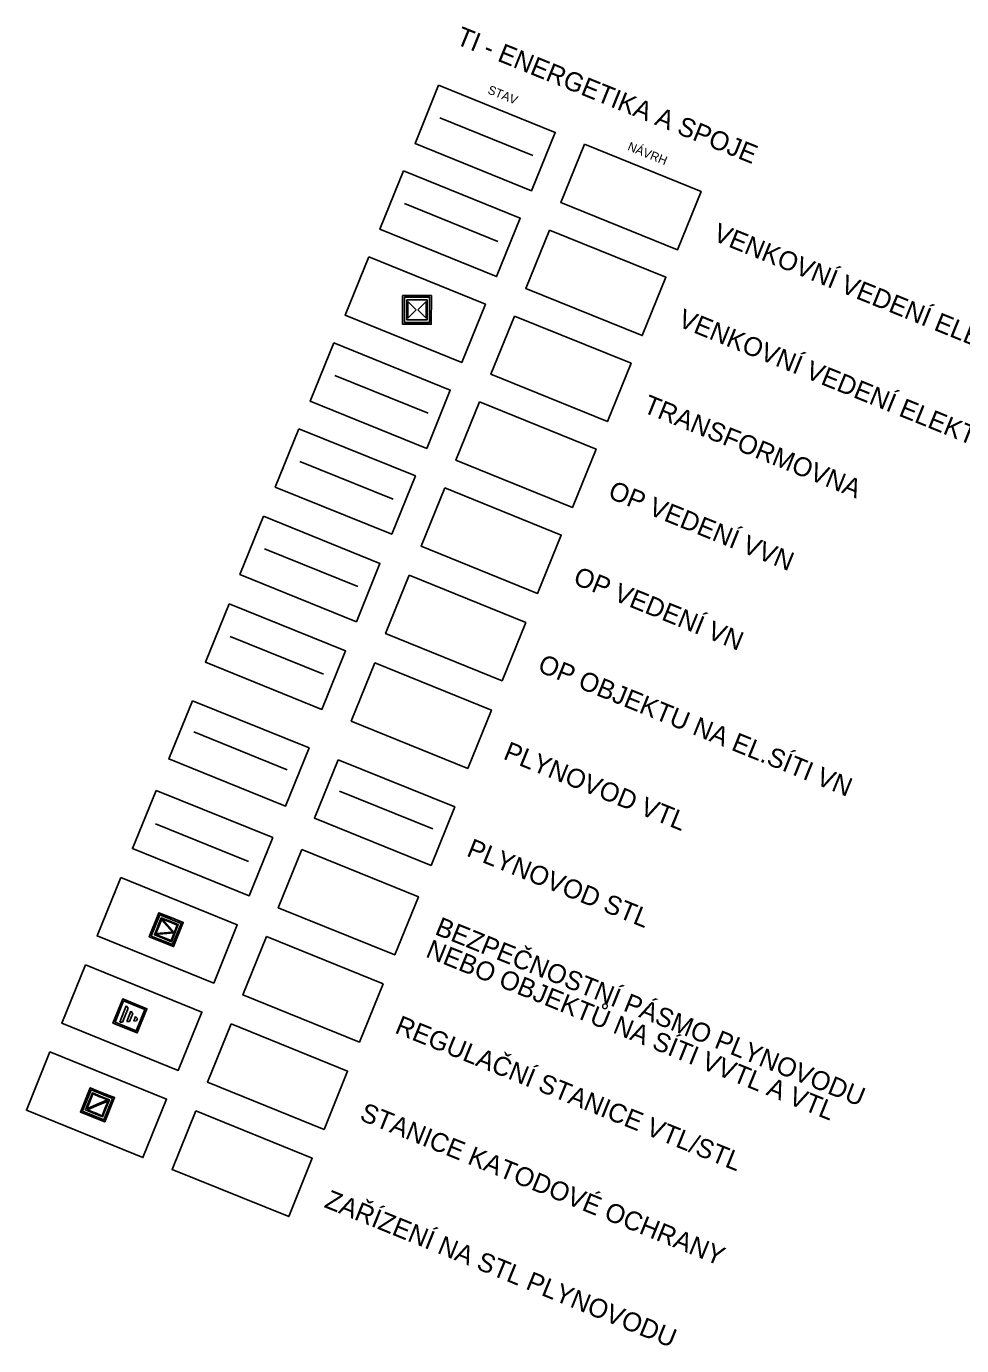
# Model space of a CAD drawing. Extents: x -522797 to -519326, y -1191143 to -1184078.
# Drawn here: x -521007 to -520263, y -1190883 to -1189835 of the extents above; entities that cross this region are included whole.
import ezdxf

# ---------------------------------------------------------------- set-up
doc = ezdxf.new("R2010")
doc.units = 0
for name, color, linetype in [('elved_110_s', 7, 'Continuous'), ('elved_22_s', 7, 'Continuous'), ('Implicitní', 7, 'Continuous'), ('ložisk_nerost', 7, 'Continuous'), ('OP_OelVN_s', 7, 'Continuous'), ('OP_VN_s', 7, 'Continuous'), ('OP_VVN_s', 7, 'Continuous'), ('plyn_STL_n', 7, 'Continuous'), ('plyn_STL_s', 7, 'Continuous'), ('plyn_VTL_s', 7, 'Continuous'), ('plyn_zar_STL_s', 7, 'Continuous'), ('stan_KO_s', 7, 'Continuous')]:
    doc.layers.add(name, color=color, linetype=linetype)

msp = doc.modelspace()

# ---------------------------------------------------------------- linework, layer by layer
at = {"layer": 'elved_110_s'}
msp.add_line((-520678, -1189907.3), (-520603.9, -1189937.4), dxfattribs=at)
at = {"layer": 'elved_22_s'}
msp.add_line((-520705.9, -1189975.5), (-520631.8, -1190005.6), dxfattribs=at)
at = {"layer": 'Implicitní'}
msp.add_line((-520904, -1190468.4), (-520829.9, -1190498.5), dxfattribs=at)
for points in [[(-520678.9, -1189881.4), (-520586.2, -1189919), (-520605, -1189965.3), (-520697.6, -1189927.7)], [(-520563, -1189928.4), (-520470.3, -1189965.9), (-520489.1, -1190012.3), (-520581.8, -1189974.7)], [(-520706.7, -1189949.6), (-520614, -1189987.2), (-520632.8, -1190033.5), (-520725.5, -1189996)], [(-520590.9, -1189996.6), (-520498.2, -1190034.1), (-520517, -1190080.5), (-520609.7, -1190042.9)], [(-520734.4, -1190017.9), (-520641.7, -1190055.5), (-520660.5, -1190101.8), (-520753.2, -1190064.3)], [(-520618.6, -1190064.9), (-520525.9, -1190102.5), (-520544.7, -1190148.8), (-520637.3, -1190111.2)], [(-520762.3, -1190086.2), (-520669.6, -1190123.7), (-520688.4, -1190170.1), (-520781.1, -1190132.5)], [(-520646.4, -1190133.1), (-520553.7, -1190170.7), (-520572.5, -1190217), (-520665.2, -1190179.5)], [(-520790, -1190154.5), (-520697.3, -1190192), (-520716.1, -1190238.4), (-520808.7, -1190200.8)], [(-520674.1, -1190201.4), (-520581.4, -1190239), (-520600.2, -1190285.3), (-520692.9, -1190247.8)], [(-520818.1, -1190224), (-520725.5, -1190261.5), (-520744.2, -1190307.9), (-520836.9, -1190270.3)], [(-520702.3, -1190270.9), (-520609.6, -1190308.5), (-520628.4, -1190354.8), (-520721.1, -1190317.3)], [(-520845.5, -1190293.6), (-520752.8, -1190331.1), (-520771.6, -1190377.5), (-520864.2, -1190339.9)], [(-520729.6, -1190340.5), (-520636.9, -1190378.1), (-520655.7, -1190424.4), (-520748.4, -1190386.8)], [(-520874.6, -1190370.6), (-520781.9, -1190408.2), (-520800.7, -1190454.5), (-520893.4, -1190416.9)], [(-520758.8, -1190417.6), (-520666.1, -1190455.1), (-520684.9, -1190501.5), (-520777.6, -1190463.9)], [(-520903.5, -1190441.9), (-520810.8, -1190479.4), (-520829.6, -1190525.8), (-520922.3, -1190488.2)], [(-520787.7, -1190488.8), (-520695, -1190526.4), (-520713.8, -1190572.7), (-520806.4, -1190535.2)], [(-520931.6, -1190511.2), (-520838.9, -1190548.7), (-520857.7, -1190595.1), (-520950.4, -1190557.5)], [(-520815.8, -1190558.1), (-520723.1, -1190595.7), (-520741.9, -1190642), (-520834.5, -1190604.5)], [(-520959.7, -1190580.5), (-520867, -1190618.1), (-520885.8, -1190664.4), (-520978.5, -1190626.8)], [(-520843.8, -1190627.4), (-520751.2, -1190665), (-520769.9, -1190711.3), (-520862.6, -1190673.8)], [(-520987.8, -1190649.8), (-520895.1, -1190687.4), (-520913.9, -1190733.7), (-521006.6, -1190696.1)], [(-520871.9, -1190696.7), (-520779.3, -1190734.3), (-520798, -1190780.6), (-520890.7, -1190743.1)]]:
    msp.add_lwpolyline(points, close=True, dxfattribs=at)
at = {"layer": 'ložisk_nerost'}
for p, q in [((-520704.1, -1190060), (-520703.4, -1190060)), ((-520703.4, -1190060), (-520704.1, -1190060)), ((-520696.8, -1190060), (-520703.4, -1190053.4)), ((-520703.4, -1190066.6), (-520696.8, -1190060)), ((-520688.8, -1190053.4), (-520695.4, -1190060)), ((-520695.4, -1190060), (-520688.8, -1190066.6)), ((-520688.1, -1190060), (-520688.8, -1190060)), ((-520688.8, -1190060), (-520688.1, -1190060))]:
    msp.add_line(p, q, dxfattribs=at)
for points in [[(-520696.1, -1190048.6), (-520707.5, -1190048.6), (-520707.5, -1190071.4), (-520684.7, -1190071.4), (-520684.6, -1190048.6), (-520696.1, -1190048.6)], [(-520706.1, -1190050), (-520686.1, -1190050), (-520686.1, -1190070), (-520706.1, -1190070), (-520706.1, -1190050)], [(-520696.1, -1190050), (-520686.1, -1190050), (-520686.1, -1190070), (-520706.1, -1190070), (-520706.1, -1190050), (-520696.1, -1190050)], [(-520696.1, -1190048.6), (-520696.1, -1190050)], [(-520696.1, -1190050), (-520696.1, -1190048.6)], [(-520704.1, -1190060), (-520704.1, -1190052), (-520696.1, -1190052)], [(-520696.1, -1190068), (-520704.1, -1190068), (-520704.1, -1190060)], [(-520703.4, -1190053.4), (-520703.4, -1190060)], [(-520703.4, -1190060), (-520703.4, -1190066.6)], [(-520696.1, -1190052), (-520688.1, -1190052), (-520688.1, -1190060)], [(-520688.1, -1190060), (-520688.1, -1190068), (-520696.1, -1190068)], [(-520688.8, -1190060), (-520688.8, -1190053.4)], [(-520688.8, -1190066.6), (-520688.8, -1190060)], [(-520891.5, -1190543), (-520901.2, -1190539.1), (-520908.9, -1190558.4), (-520889.6, -1190566.1), (-520881.9, -1190546.9), (-520891.5, -1190543)], [(-520892, -1190544.2), (-520883.5, -1190547.6), (-520890.3, -1190564.5), (-520907.3, -1190557.7), (-520900.5, -1190540.7), (-520892, -1190544.1)], [(-520900.5, -1190540.8), (-520883.5, -1190547.6), (-520890.3, -1190564.5), (-520907.3, -1190557.7), (-520900.5, -1190540.8)], [(-520902, -1190549.9), (-520899.3, -1190543.2), (-520892.5, -1190545.9)], [(-520891.5, -1190543), (-520892, -1190544.2)], [(-520892, -1190544.1), (-520891.5, -1190543)], [(-520898, -1190559.4), (-520904.8, -1190556.7), (-520902, -1190550)], [(-520901.4, -1190550.2), (-520903.6, -1190555.6)], [(-520901.4, -1190550.2), (-520902, -1190549.9)], [(-520902, -1190550), (-520901.4, -1190550.2)], [(-520899.2, -1190544.7), (-520901.4, -1190550.2)], [(-520890.5, -1190554.6), (-520899.2, -1190544.7)], [(-520892.8, -1190546.5), (-520899, -1190544)], [(-520899, -1190544), (-520889.1, -1190555.1)], [(-520892.5, -1190545.9), (-520892.8, -1190546.5)], [(-520892.7, -1190546.5), (-520892.5, -1190545.9)], [(-520886.6, -1190549), (-520892.7, -1190546.5)], [(-520892.5, -1190545.9), (-520885.8, -1190548.6), (-520888.5, -1190555.4)], [(-520891.6, -1190561.3), (-520886.6, -1190549)], [(-520889.1, -1190555.1), (-520903.9, -1190556.4)], [(-520903.9, -1190556.4), (-520897.7, -1190558.9)], [(-520903.6, -1190555.6), (-520890.5, -1190554.6)], [(-520888.5, -1190555.4), (-520891.2, -1190562.2), (-520898, -1190559.4)], [(-520897.7, -1190558.9), (-520891.6, -1190561.3)]]:
    msp.add_lwpolyline(points, dxfattribs=at)
at = {"layer": 'OP_OelVN_s'}
msp.add_line((-520817.3, -1190249.9), (-520743.2, -1190279.9), dxfattribs=at)
at = {"layer": 'OP_VN_s'}
msp.add_line((-520789.1, -1190180.4), (-520715, -1190210.4), dxfattribs=at)
at = {"layer": 'OP_VVN_s'}
msp.add_line((-520761.5, -1190112.1), (-520687.3, -1190142.1), dxfattribs=at)
at = {"layer": 'plyn_STL_n'}
msp.add_line((-520757.6, -1190442.5), (-520683.4, -1190472.5), dxfattribs=at)
at = {"layer": 'plyn_STL_s'}
msp.add_line((-520873.4, -1190395.5), (-520799.3, -1190425.6), dxfattribs=at)
at = {"layer": 'plyn_VTL_s'}
msp.add_line((-520844.6, -1190319.5), (-520770.5, -1190349.5), dxfattribs=at)
at = {"layer": 'plyn_zar_STL_s'}
for p, q in [((-520942, -1190687.9), (-520950.7, -1190691.6)), ((-520950.3, -1190692.4), (-520941.6, -1190688.8)), ((-520947.6, -1190685.7), (-520947.3, -1190685.1)), ((-520947.3, -1190685.1), (-520947.5, -1190685.7)), ((-520950.7, -1190691.6), (-520958.5, -1190694.9)), ((-520958.1, -1190695.7), (-520950.3, -1190692.4)), ((-520952.8, -1190698.6), (-520952.6, -1190698)), ((-520952.5, -1190698), (-520952.8, -1190698.6))]:
    msp.add_line(p, q, dxfattribs=at)
for points in [[(-520946.2, -1190682.2), (-520955.8, -1190678.3), (-520963.6, -1190697.6), (-520944.3, -1190705.4), (-520936.5, -1190686.1), (-520946.2, -1190682.2)], [(-520955.1, -1190680), (-520938.2, -1190686.8), (-520945, -1190703.7), (-520962, -1190696.9), (-520955.1, -1190680)], [(-520946.6, -1190683.4), (-520938.2, -1190686.8), (-520945, -1190703.7), (-520962, -1190696.9), (-520955.1, -1190680), (-520946.7, -1190683.4)], [(-520956.8, -1190689.1), (-520959.6, -1190695.9), (-520952.8, -1190698.6)], [(-520958.5, -1190694.9), (-520956.2, -1190689.3)], [(-520947.3, -1190685.1), (-520954.1, -1190682.3), (-520956.8, -1190689.1)], [(-520956.2, -1190689.3), (-520953.7, -1190683.2)], [(-520953.7, -1190683.2), (-520947.6, -1190685.7)], [(-520947.5, -1190685.7), (-520942, -1190687.9)], [(-520943.3, -1190694.6), (-520940.6, -1190687.8), (-520947.3, -1190685.1)], [(-520946.7, -1190683.4), (-520946.2, -1190682.2)], [(-520946.2, -1190682.2), (-520946.6, -1190683.4)], [(-520941.6, -1190688.8), (-520943.9, -1190694.3)], [(-520952.6, -1190698), (-520958.1, -1190695.7)], [(-520952.8, -1190698.6), (-520946.1, -1190701.3), (-520943.3, -1190694.6)], [(-520946.4, -1190700.5), (-520952.5, -1190698)], [(-520943.9, -1190694.3), (-520946.4, -1190700.5)]]:
    msp.add_lwpolyline(points, dxfattribs=at)
at = {"layer": 'stan_KO_s'}
for points in [[(-520920.3, -1190611.5), (-520930, -1190607.6), (-520937.8, -1190626.8), (-520918.5, -1190634.7), (-520910.7, -1190615.4), (-520920.3, -1190611.5)], [(-520929.3, -1190609.2), (-520912.4, -1190616.1), (-520919.2, -1190633), (-520936.1, -1190626.1), (-520929.3, -1190609.2)], [(-520920.8, -1190612.7), (-520912.4, -1190616.1), (-520919.2, -1190633), (-520936.1, -1190626.1), (-520929.3, -1190609.2), (-520920.8, -1190612.6)], [(-520932.4, -1190626.1), (-520927.2, -1190613.2)], [(-520925.7, -1190614.9), (-520930.2, -1190626)], [(-520927.2, -1190613.2), (-520925.7, -1190614.9)], [(-520920.3, -1190611.5), (-520920.8, -1190612.7)], [(-520920.8, -1190612.6), (-520920.3, -1190611.5)], [(-520930.2, -1190626), (-520932.4, -1190626.1)], [(-520926.8, -1190625.7), (-520923.5, -1190617.4)], [(-520924.6, -1190625.5), (-520926.8, -1190625.7)], [(-520922, -1190619.1), (-520924.6, -1190625.5)], [(-520923.5, -1190617.4), (-520922, -1190619.1)], [(-520921.2, -1190625.3), (-520919.8, -1190621.6)], [(-520919, -1190625.1), (-520921.2, -1190625.3)], [(-520919.8, -1190621.6), (-520918.3, -1190623.3)], [(-520918.3, -1190623.3), (-520919, -1190625.1)]]:
    msp.add_lwpolyline(points, dxfattribs=at)

# ---------------------------------------------------------------- texts
at = {"layer": 'Implicitní'}
for s, height, p in [('TI - ENERGETIKA A SPOJE', 15, (-520666, -1189848.4)), ('STAV', 7, (-520640.5, -1189887.8)), ('NÁVRH', 7, (-520529.3, -1189932.8)), ('VENKOVNÍ VEDENÍ ELEKTRICKÉ SÍTĚ 110 kV', 15, (-520461.7, -1190004.5)), ('VENKOVNÍ VEDENÍ ELEKTRICKÉ SÍTĚ 22 kV', 15, (-520489.6, -1190072.7)), ('TRANSFORMOVNA', 15, (-520517.3, -1190141)), ('OP VEDENÍ VVN', 15, (-520545.1, -1190209.2)), ('OP VEDENÍ VN', 15, (-520572.8, -1190277.5)), ('OP OBJEKTU NA EL.SÍTI VN', 15, (-520601, -1190347.1)), ('PLYNOVOD VTL', 15, (-520628.3, -1190416.6)), ('PLYNOVOD STL', 15, (-520657.5, -1190493.7)), ('BEZPEČNOSTNÍ PÁSMO PLYNOVODU ', 15, (-520682.7, -1190556)), ('NEBO OBJEKTŮ NA SÍTI VVTL A VTL', 15, (-520690, -1190573.9)), ('REGULAČNÍ STANICE VTL/STL', 15, (-520714.5, -1190634.3)), ('STANICE KATODOVÉ OCHRANY', 15, (-520742.5, -1190703.6)), ('ZAŘÍZENÍ NA STL PLYNOVODU', 15, (-520770.6, -1190772.9))]:
    msp.add_text(s, height=height, rotation=337.9379, dxfattribs=at).set_placement(p)

doc.saveas('drawing.dxf')
